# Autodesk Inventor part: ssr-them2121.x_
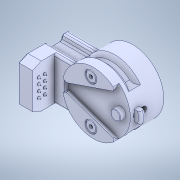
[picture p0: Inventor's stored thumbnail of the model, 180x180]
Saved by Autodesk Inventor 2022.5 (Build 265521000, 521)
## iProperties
Created: 2022-03
Part Number: ssr-them2121.x_
Material: 一般
Document SubType Name: Modeling
Designer: ImaoCorp
Density: 1 g/cm^3
Appearance: 既定
Sending System: SOLIDWORKS 2016-2016286
MC: AMD64
MC_MODEL: Intel64 Family 6 Model 158 Stepping 10, GenuineIntel
OS: Windows_NT
FRU: Parasolid Version 28.0, build 224,  7-29-2016
FORMAT: text
GUISE: transmit
KEY: ssr-them2121
FILE: ssr-them2121.x_t
DATE: Mon Mar 14 14:02:52 2022
Author: ImaoCorp
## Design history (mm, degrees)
feature "Base1"
node "ソリッド1"
